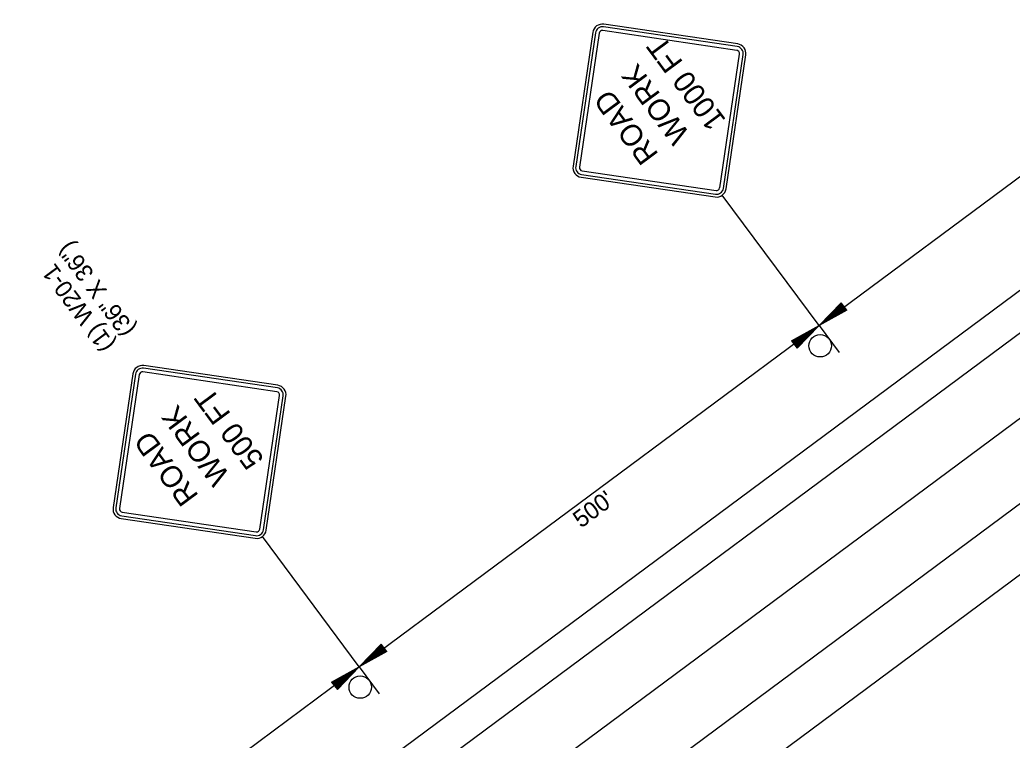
# Model space of a CAD drawing. Extents: x -238 to 1487, y -1123 to 446.
# Drawn here: x 783.5 to 1130, y -232.3 to 19.3 of the extents above; entities that cross this region are included whole.
import ezdxf

# ---------------------------------------------------------------- set-up
doc = ezdxf.new("R2010")
doc.units = 0
for name, color, linetype in [('P_TC_Signs_Temporary', 7, 'Continuous'), ('R_Border Prem', 7, 'Continuous'), ('R_Draft', 7, 'Continuous'), ('STAMP', 7, 'Continuous')]:
    doc.layers.add(name, color=color, linetype=linetype)

msp = doc.modelspace()

# ---------------------------------------------------------------- linework, layer by layer
at = {"layer": 'P_TC_Signs_Temporary'}
for p, q in [((1034.14, 10.85), (987.4, 17.76)), ((983.57, 14.92), (976.66, -31.83)), ((984.49, 14.78), (977.59, -31.96)), ((985.79, 14.59), (978.89, -32.16)), ((1033.81, 8.63), (987.07, 15.54)), ((1034, 9.93), (987.26, 16.83)), ((1027.85, -39.39), (1034.76, 7.35)), ((1029.15, -39.58), (1036.06, 7.16)), ((1030.08, -39.72), (1036.99, 7.02)), ((979.83, -33.43), (1026.58, -40.34)), ((979.51, -35.66), (1026.25, -42.57)), ((979.64, -34.73), (1026.38, -41.64)), ((873.24, -110.6), (826.5, -103.7)), ((873.43, -109.3), (826.69, -102.4)), ((873.57, -108.38), (826.82, -101.47)), ((822.99, -104.32), (816.09, -151.06)), ((823.92, -104.45), (817.01, -151.2)), ((825.22, -104.64), (818.31, -151.39)), ((867.28, -158.62), (874.19, -111.88)), ((868.58, -158.81), (875.49, -112.07)), ((869.51, -158.95), (876.41, -112.21)), ((818.93, -154.89), (865.67, -161.8)), ((819.07, -153.96), (865.81, -160.87)), ((819.26, -152.66), (866, -159.57))]:
    msp.add_line(p, q, dxfattribs=at)
for centre, radius, start, end in [((986.9, 14.42), 3.38, 81.5953, 171.5953), ((986.9, 14.42), 2.44, 81.5953, 171.5953), ((986.9, 14.42), 1.12, 81.5953, 171.5953), ((1033.65, 7.52), 3.38, 351.5953, 81.5953), ((1033.65, 7.52), 1.13, 351.5953, 81.5953), ((1033.65, 7.52), 2.44, 351.5953, 81.5953), ((980, -32.32), 3.38, 171.5953, 261.5953), ((980, -32.32), 2.44, 171.5953, 261.5953), ((980, -32.32), 1.13, 171.5953, 261.5953), ((1026.74, -39.23), 3.38, 261.5953, 351.5953), ((1026.74, -39.23), 2.44, 261.5953, 351.5953), ((1026.74, -39.23), 1.12, 261.5953, 351.5953), ((826.33, -104.81), 3.38, 81.5953, 171.5953), ((826.33, -104.81), 2.44, 81.5953, 171.5953), ((826.33, -104.81), 1.12, 81.5953, 171.5953), ((873.07, -111.72), 1.13, 351.5953, 81.5953), ((873.07, -111.72), 2.44, 351.5953, 81.5953), ((873.07, -111.72), 3.38, 351.5953, 81.5953), ((819.43, -151.55), 3.38, 171.5953, 261.5953), ((819.43, -151.55), 2.44, 171.5953, 261.5953), ((819.43, -151.55), 1.13, 171.5953, 261.5953), ((866.17, -158.46), 3.38, 261.5953, 351.5953), ((866.17, -158.46), 2.44, 261.5953, 351.5953), ((866.17, -158.46), 1.12, 261.5953, 351.5953)]:
    msp.add_arc(centre, radius, start, end, dxfattribs=at)
at = {"layer": 'R_Draft'}
for p, q in [((1062.58, -87.49), (1223.15, 31.74)), ((1242.19, 6.1), (691.32, -402.94)), ((1249.33, -3.51), (698.46, -412.55)), ((1263.6, -22.73), (712.73, -431.77)), ((1277.87, -41.95), (727, -450.98)), ((1062.58, -87.49), (1028.75, -41.94)), ((1289.76, -57.96), (738.89, -467)), ((1070.22, -79.57), (1062.58, -87.49)), ((1072.2, -82.16), (1070.22, -79.57)), ((1072.2, -82.16), (1062.58, -87.49)), ((1070.38, -79.78), (1064.02, -86.38)), ((1072.04, -81.94), (1064.02, -86.38)), ((1070.55, -80.01), (1065.5, -85.25)), ((1071.87, -81.72), (1065.5, -85.25)), ((1070.72, -80.22), (1066.94, -84.14)), ((1071.7, -81.51), (1066.94, -84.14)), ((1070.89, -80.44), (1068.41, -83.02)), ((1071.53, -81.29), (1068.41, -83.02)), ((1071.06, -80.66), (1069.84, -81.91)), ((1071.36, -81.07), (1069.84, -81.91)), ((1062.58, -87.49), (902.01, -206.72)), ((1052.96, -92.82), (1062.58, -87.49)), ((1053.12, -93.04), (1061.14, -88.6)), ((1053.29, -93.26), (1059.66, -89.74)), ((1054.61, -94.98), (1059.66, -89.74)), ((1054.78, -95.19), (1061.14, -88.6)), ((1054.94, -95.41), (1062.58, -87.49)), ((1052.96, -92.82), (1054.94, -95.41)), ((1053.46, -93.47), (1058.22, -90.84)), ((1053.63, -93.7), (1056.75, -91.96)), ((1053.79, -93.92), (1055.31, -93.07)), ((1054.1, -94.32), (1055.31, -93.07)), ((1054.27, -94.54), (1056.75, -91.96)), ((1054.44, -94.76), (1058.22, -90.84)), ((902.01, -206.72), (868.18, -161.17)), ((909.64, -198.8), (902.01, -206.72)), ((909.81, -199.02), (903.45, -205.61)), ((909.98, -199.24), (904.93, -204.48)), ((910.15, -199.45), (906.37, -203.37)), ((911.13, -200.74), (906.37, -203.37)), ((910.31, -199.67), (907.83, -202.25)), ((910.96, -200.52), (907.83, -202.25)), ((910.48, -199.89), (909.27, -201.14)), ((910.79, -200.3), (909.27, -201.14)), ((911.63, -201.39), (909.64, -198.8)), ((911.63, -201.39), (902.01, -206.72)), ((911.47, -201.18), (903.45, -205.61)), ((911.29, -200.96), (904.93, -204.48)), ((741.43, -325.95), (902.01, -206.72)), ((892.38, -212.05), (902.01, -206.72)), ((892.55, -212.27), (900.57, -207.83)), ((894.2, -214.43), (900.57, -207.83)), ((894.37, -214.65), (902.01, -206.72)), ((892.72, -212.49), (899.08, -208.97)), ((892.88, -212.71), (897.65, -210.07)), ((893.06, -212.93), (896.18, -211.2)), ((893.7, -213.77), (896.18, -211.2)), ((893.87, -213.99), (897.65, -210.07)), ((894.03, -214.21), (899.08, -208.97)), ((892.38, -212.05), (894.37, -214.65)), ((893.22, -213.15), (894.74, -212.31)), ((893.53, -213.55), (894.74, -212.31))]:
    msp.add_line(p, q, dxfattribs=at)
at = {"layer": 'STAMP'}
for p, q in [((1062.58, -87.49), (1069.58, -96.93)), ((902.01, -206.72), (909.01, -216.16))]:
    msp.add_line(p, q, dxfattribs=at)
for centre in [(1062.93, -94.55), (902.36, -213.78)]:
    msp.add_circle(centre, 3.92, dxfattribs=at)

# ---------------------------------------------------------------- texts
at = {"layer": 'P_TC_Signs_Temporary'}
for s, p in [('1000 FT', (1030.27, -15.74)), ('WORK', (1017.68, -20.63)), (' ROAD ', (1008.38, -29.95)), ('500 FT ', (869.05, -134.11)), ('WORK', (857.1, -139.86)), (' ROAD ', (847.81, -149.19))]:
    msp.add_text(s, height=7.5, rotation=126.5953, dxfattribs=at).set_placement(p)
at = {"layer": 'R_Border Prem'}
for s, rotation, p in [('(36" X 36")', 126.5953, (824.13, -88.66)), ('(1) W20-1', 126.5953, (816.91, -94.03)), ("500'", 36.5953, (979.47, -158.45))]:
    msp.add_text(s, height=6, rotation=rotation, dxfattribs=at).set_placement(p)

doc.saveas('drawing.dxf')
